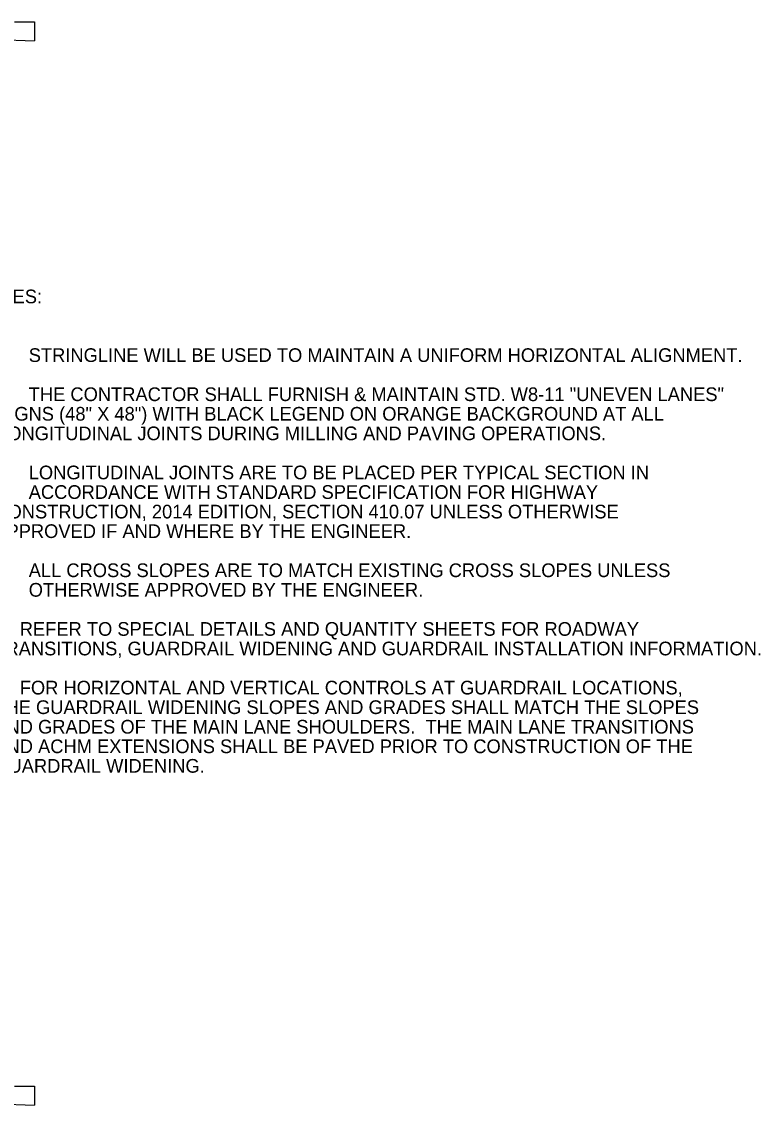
# Model space of a CAD drawing. Extents: x 545241 to 1930787, y -1971772 to 596640.
# Drawn here: x 547832 to 548210, y -1958561 to -1958007 of the extents above; entities that cross this region are included whole.
import ezdxf

# ---------------------------------------------------------------- set-up
doc = ezdxf.new("R2010")
doc.units = 0
for name, color, linetype in [('R_Border', 7, 'Continuous'), ('R_Border Notes', 7, 'Continuous'), ('R_Draft', 7, 'Continuous')]:
    doc.layers.add(name, color=color, linetype=linetype)

msp = doc.modelspace()

# ---------------------------------------------------------------- linework, layer by layer
at = {"layer": 'R_Border'}
for p, q in [((547828.13, -1958007.42), (547838.3, -1958007.42)), ((547838.3, -1958007.42), (547838.3, -1958017.23)), ((547828.13, -1958551.64), (547838.3, -1958551.64)), ((547838.3, -1958551.64), (547838.3, -1958561.45))]:
    msp.add_line(p, q, dxfattribs=at)
at = {"layer": 'R_Draft'}
for p, q in [((547748.13, -1958013.63), (547838.3, -1958017.23)), ((547748.13, -1958557.85), (547838.3, -1958561.45))]:
    msp.add_line(p, q, dxfattribs=at)

# ---------------------------------------------------------------- texts
at = {"layer": 'R_Border Notes'}
for s, p in [('NOTES: ', (547807.36, -1958151.4)), ('STRINGLINE WILL BE USED TO MAINTAIN A UNIFORM HORIZONTAL ALIGNMENT.', (547835.36, -1958181.4)), ('THE CONTRACTOR SHALL FURNISH & MAINTAIN STD. W8-11 "UNEVEN LANES" ', (547835.36, -1958201.4)), ('    SIGNS (48" X 48") WITH BLACK LEGEND ON ORANGE BACKGROUND AT ALL ', (547808.76, -1958211.4)), ('    LONGITUDINAL JOINTS DURING MILLING AND PAVING OPERATIONS.', (547808.76, -1958221.4)), ('LONGITUDINAL JOINTS ARE TO BE PLACED PER TYPICAL SECTION IN ', (547835.36, -1958241.4)), ('ACCORDANCE WITH STANDARD SPECIFICATION FOR HIGHWAY', (547835.36, -1958251.4)), ('    CONSTRUCTION, 2014 EDITION, SECTION 410.07 UNLESS OTHERWISE', (547807.36, -1958261.4)), ('    APPROVED IF AND WHERE BY THE ENGINEER.', (547807.36, -1958271.4)), ('ALL CROSS SLOPES ARE TO MATCH EXISTING CROSS SLOPES UNLESS ', (547835.36, -1958291.4)), ('OTHERWISE APPROVED BY THE ENGINEER.', (547835.36, -1958301.4)), ('5.      REFER TO SPECIAL DETAILS AND QUANTITY SHEETS FOR ROADWAY', (547807.36, -1958321.4)), ('    TRANSITIONS, GUARDRAIL WIDENING AND GUARDRAIL INSTALLATION INFORMATION.', (547807.36, -1958331.4)), ('6.      FOR HORIZONTAL AND VERTICAL CONTROLS AT GUARDRAIL LOCATIONS,', (547807.36, -1958351.4)), ('    THE GUARDRAIL WIDENING SLOPES AND GRADES SHALL MATCH THE SLOPES', (547807.36, -1958361.4)), ('    AND GRADES OF THE MAIN LANE SHOULDERS.  THE MAIN LANE TRANSITIONS', (547807.36, -1958371.4)), ('    AND ACHM EXTENSIONS SHALL BE PAVED PRIOR TO CONSTRUCTION OF THE', (547807.36, -1958381.4)), ('    GUARDRAIL WIDENING.', (547807.36, -1958391.4))]:
    msp.add_text(s, height=7, dxfattribs=at).set_placement(p)

doc.saveas('drawing.dxf')
